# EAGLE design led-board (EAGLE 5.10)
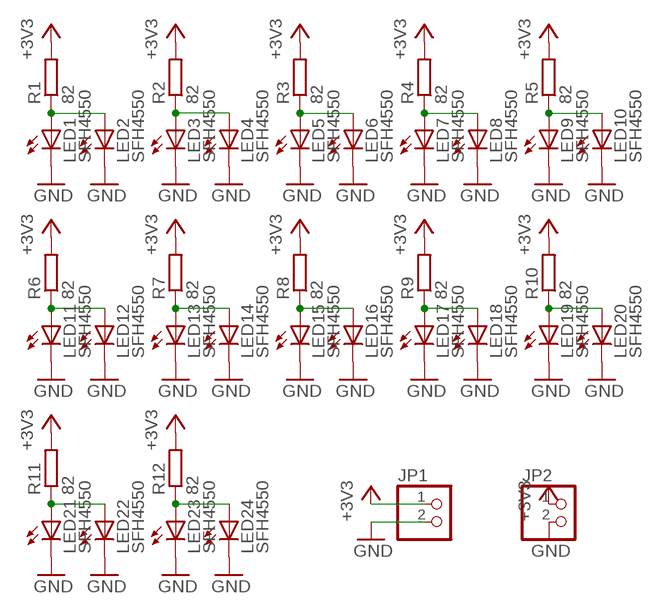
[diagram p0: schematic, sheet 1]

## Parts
JP1  PINHD-1X2  [1X02]
JP2  PINHD-1X2  [1X02]
LED1  SFH4550  LED5MM  [LED5MM]
LED2  SFH4550  LED5MM  [LED5MM]
LED3  SFH4550  LED5MM  [LED5MM]
LED4  SFH4550  LED5MM  [LED5MM]
LED5  SFH4550  LED5MM  [LED5MM]
LED6  SFH4550  LED5MM  [LED5MM]
LED7  SFH4550  LED5MM  [LED5MM]
LED8  SFH4550  LED5MM  [LED5MM]
LED9  SFH4550  LED5MM  [LED5MM]
LED10  SFH4550  LED5MM  [LED5MM]
LED11  SFH4550  LED5MM  [LED5MM]
LED12  SFH4550  LED5MM  [LED5MM]
LED13  SFH4550  LED5MM  [LED5MM]
LED14  SFH4550  LED5MM  [LED5MM]
LED15  SFH4550  LED5MM  [LED5MM]
LED16  SFH4550  LED5MM  [LED5MM]
LED17  SFH4550  LED5MM  [LED5MM]
LED18  SFH4550  LED5MM  [LED5MM]
LED19  SFH4550  LED5MM  [LED5MM]
LED20  SFH4550  LED5MM  [LED5MM]
LED21  SFH4550  LED5MM  [LED5MM]
LED22  SFH4550  LED5MM  [LED5MM]
LED23  SFH4550  LED5MM  [LED5MM]
LED24  SFH4550  LED5MM  [LED5MM]
R1  82  R-EU_M1206  [M1206]
R2  82  R-EU_M1206  [M1206]
R3  82  R-EU_M1206  [M1206]
R4  82  R-EU_M1206  [M1206]
R5  82  R-EU_M1206  [M1206]
R6  82  R-EU_M1206  [M1206]
R7  82  R-EU_M1206  [M1206]
R8  82  R-EU_M1206  [M1206]
R9  82  R-EU_M1206  [M1206]
R10  82  R-EU_M1206  [M1206]
R11  82  R-EU_M1206  [M1206]
R12  82  R-EU_M1206  [M1206]

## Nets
+3V3: JP1.1 JP2.1 R1.2 R2.2 R3.2 R4.2 R5.2 R6.2 R7.2 R8.2 R9.2 R10.2 R11.2 R12.2
GND: JP1.2 JP2.2 LED1.K(C) LED2.K(C) LED3.K(C) LED4.K(C) LED5.K(C) LED6.K(C) LED7.K(C) LED8.K(C) LED9.K(C) LED10.K(C) LED11.K(C) LED12.K(C) LED13.K(C) LED14.K(C) LED15.K(C) LED16.K(C) LED17.K(C) LED18.K(C) LED19.K(C) LED20.K(C) LED21.K(C) LED22.K(C) LED23.K(C) LED24.K(C)
N$1: LED1.A LED2.A R1.1
N$2: LED3.A LED4.A R2.1
N$3: LED5.A LED6.A R3.1
N$4: LED7.A LED8.A R4.1
N$5: LED9.A LED10.A R5.1
N$6: LED19.A LED20.A R10.1
N$7: LED17.A LED18.A R9.1
N$8: LED15.A LED16.A R8.1
N$9: LED13.A LED14.A R7.1
N$10: LED11.A LED12.A R6.1
N$11: LED21.A LED22.A R11.1
N$12: LED23.A LED24.A R12.1

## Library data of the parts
JP1 JP2 = pinhead:PINHD-1X2: PIN HEADER
LED1-LED24 = led:LED: LED
R1-R12 = rcl:R-EU_: RESISTOR, European symbol

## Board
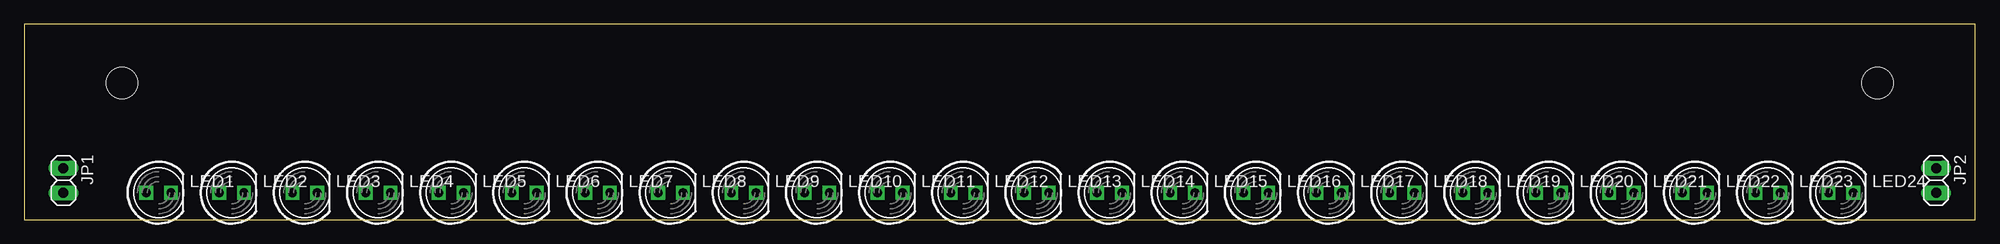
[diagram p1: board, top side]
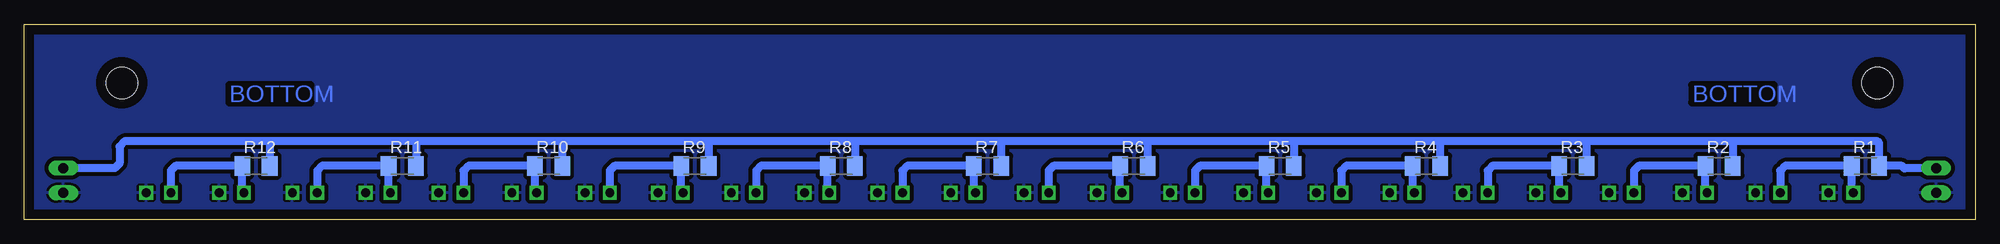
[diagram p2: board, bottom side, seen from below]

Size 200 x 20 mm. Coordinates in mm from the lower left corner, seen from the top.
Outline: 0,0 200,0 200,20 0,20 0,0
Copper layers (1*16): Top 0.035mm / dielectric 1.5mm / Bottom 0.035mm
Design rules "default": minimum track width 10mil, minimum drill 24mil, track to track 8mil, track to pad 8mil, pad to pad 8mil, via to via 8mil, smd to smd 8mil, copper to edge 40mil, drill to drill 8mil, minimum pad ring 10mil, minimum via ring 8mil, stop-mask expansion 4mil, vias tented up to drill 0mil, thermal gap 10mil
Holes 3.2 mm at 10,14 190,14

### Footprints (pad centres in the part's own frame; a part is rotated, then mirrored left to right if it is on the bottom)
1X02 = drill 1.016 long: 1 -1.27,0; 2 1.27,0
LED5MM = drill 0.9 square: A -1.27,0; K 1.27,0
M1206 = smd 1.6 x 2: 1 -1.4,0; 2 1.4,0

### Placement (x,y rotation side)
JP1  4,4 270 top
JP2  196,4 270 top
LED1  13.75,2.75 0 top
LED2  21.25,2.75 0 top
LED3  28.75,2.75 0 top
LED4  36.25,2.75 0 top
LED5  43.75,2.75 0 top
LED6  51.25,2.75 0 top
LED7  58.75,2.75 0 top
LED8  66.25,2.75 0 top
LED9  73.75,2.75 0 top
LED10  81.25,2.75 0 top
LED11  88.75,2.75 0 top
LED12  96.25,2.75 0 top
LED13  103.75,2.75 0 top
LED14  111.25,2.75 0 top
LED15  118.75,2.75 0 top
LED16  126.25,2.75 0 top
LED17  133.75,2.75 0 top
LED18  141.25,2.75 0 top
LED19  148.75,2.75 0 top
LED20  156.25,2.75 0 top
LED21  163.75,2.75 0 top
LED22  171.25,2.75 0 top
LED23  178.75,2.75 0 top
LED24  186.25,2.75 0 top
R1  11.25,5.5 0 bottom
R2  26.25,5.5 0 bottom
R3  41.25,5.5 0 bottom
R4  56.25,5.5 0 bottom
R5  71.25,5.5 0 bottom
R6  86.25,5.5 0 bottom
R7  101.25,5.5 0 bottom
R8  116.25,5.5 0 bottom
R9  131.25,5.5 0 bottom
R10  146.25,5.5 0 bottom
R11  161.25,5.5 0 bottom
R12  176.25,5.5 0 bottom

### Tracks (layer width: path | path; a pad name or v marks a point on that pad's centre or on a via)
+3V3
  Bottom 0.813: JP1.1 7.23,5.27 7.25,5.25 7.5,5.5 R1.2 9.85,7.85 10,8 25,8 | 25,8 40,8 | 40,8 54.75,8 | 54.75,8 69.75,8 | 69.75,8 84.75,8 | 84.75,8 99.75,8 | 99.75,8 115,8 | 115,8 130,8 | 130,8 145,8 | 145,8 160,8 | R11.2 159.85,7.85 160,8 | R10.2 144.85,7.85 145,8 | R9.2 129.85,7.85 130,8 | R8.2 114.85,7.85 115,8 | R7.2 99.85,7.9 99.75,8 | R6.2 84.85,7.9 84.75,8 | R5.2 69.85,7.9 69.75,8 | R4.2 54.85,7.9 54.75,8 | R3.2 39.85,7.85 40,8 | R2.2 24.85,7.85 25,8 | 160,8 175,8 | 175,8 189.75,8 190.25,7.5 190.25,5.75 190.73,5.27 JP2.1 | R12.2 174.85,7.85 175,8
GND
  pour Bottom (isolate 0.406): 1,0 200,0 200,20 0,20 0,0
N$1
  Bottom 0.813: LED1.A 12.65,2.92 R1.1 19.5,5.5 19.98,5.02 LED2.A
N$2
  Bottom 0.813: LED4.A 34.98,5.02 34.5,5.5 R2.1 27.65,2.92 LED3.A
N$3
  Bottom 0.813: LED5.A 42.65,2.92 R3.1 49.5,5.5 49.98,5.02 LED6.A
N$4
  Bottom 0.813: LED7.A 57.65,2.92 R4.1 64.5,5.5 64.98,5.02 LED8.A
N$5
  Bottom 0.813: LED10.A 79.98,5.02 79.5,5.5 R5.1 72.65,2.92 LED9.A
N$6
  Bottom 0.813: LED19.A 147.65,2.92 R10.1 154.5,5.5 154.98,5.02 LED20.A
N$7
  Bottom 0.813: LED17.A 132.65,2.92 R9.1 139.5,5.5 139.98,5.02 LED18.A
N$8
  Bottom 0.813: LED15.A 117.65,2.92 R8.1 124.5,5.5 124.98,5.02 LED16.A
N$9
  Bottom 0.813: LED13.A 102.65,2.92 R7.1 109.5,5.5 109.98,5.02 LED14.A
N$10
  Bottom 0.813: LED12.A 94.98,5.02 94.5,5.5 R6.1 87.65,2.92 LED11.A
N$11
  Bottom 0.813: LED21.A 162.65,2.92 R11.1 169.5,5.5 169.98,5.02 LED22.A
N$12
  Bottom 0.813: LED23.A 177.65,2.92 R12.1 184.5,5.5 184.98,5.02 LED24.A

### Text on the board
Bottom: BOTTOM | BOTTOM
